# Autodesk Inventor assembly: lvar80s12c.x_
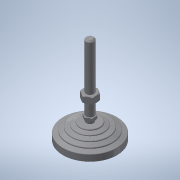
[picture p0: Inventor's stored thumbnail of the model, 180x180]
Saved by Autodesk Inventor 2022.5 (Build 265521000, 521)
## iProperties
Part Number: lvar80s12c.x_
Material: 一般
Document SubType Name: Assembly
Designer: ImaoCorp
Sending System: SOLIDWORKS 2017-2017317
MC: AMD64
MC_MODEL: Intel64 Family 6 Model 60 Stepping 3, GenuineIntel
OS: Windows_NT
FRU: Parasolid Version 29.0, build 201,  4-17-2017
FORMAT: text
GUISE: transmit
KEY: lvar80s12c
FILE: lvar80s12c.x_t
DATE: Mon Jul 01 18:15:56 2019
Author: ImaoCorp
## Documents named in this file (3)
- X:\14_SW2022-Inv2022\00_全2023-1023新製品(TCC)まで\l\lvar80s12c\LVAR80S12C.iam
- X:\14_SW2022-Inv2022\00_全2023-1023新製品(TCC)まで\l\lvar80s12c\lvar80s12c_01.ipt
- X:\14_SW2022-Inv2022\00_全2023-1023新製品(TCC)まで\l\lvar80s12c\lvar80s12c_02.ipt
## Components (2 placed, 2 different names)
1. lvar80s12c_01
2. lvar80s12c_02
